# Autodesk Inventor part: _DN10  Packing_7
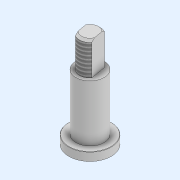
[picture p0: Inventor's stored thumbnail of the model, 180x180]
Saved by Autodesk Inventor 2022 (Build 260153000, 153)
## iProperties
Created: 2021-12
Part Number: _DN10  Packing_7
Material: Generico
Document SubType Name: Modeling
Designer: admin
Density: 1 g/cm^3
Appearance: Default
Author: admin
Revision Number: NONE
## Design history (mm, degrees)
feature "_DN10  Packing"
feature "Filettatura1" dims "d0" = 15, "d1" = 0
node "Piano di lavoro1"
node "Solido1"
